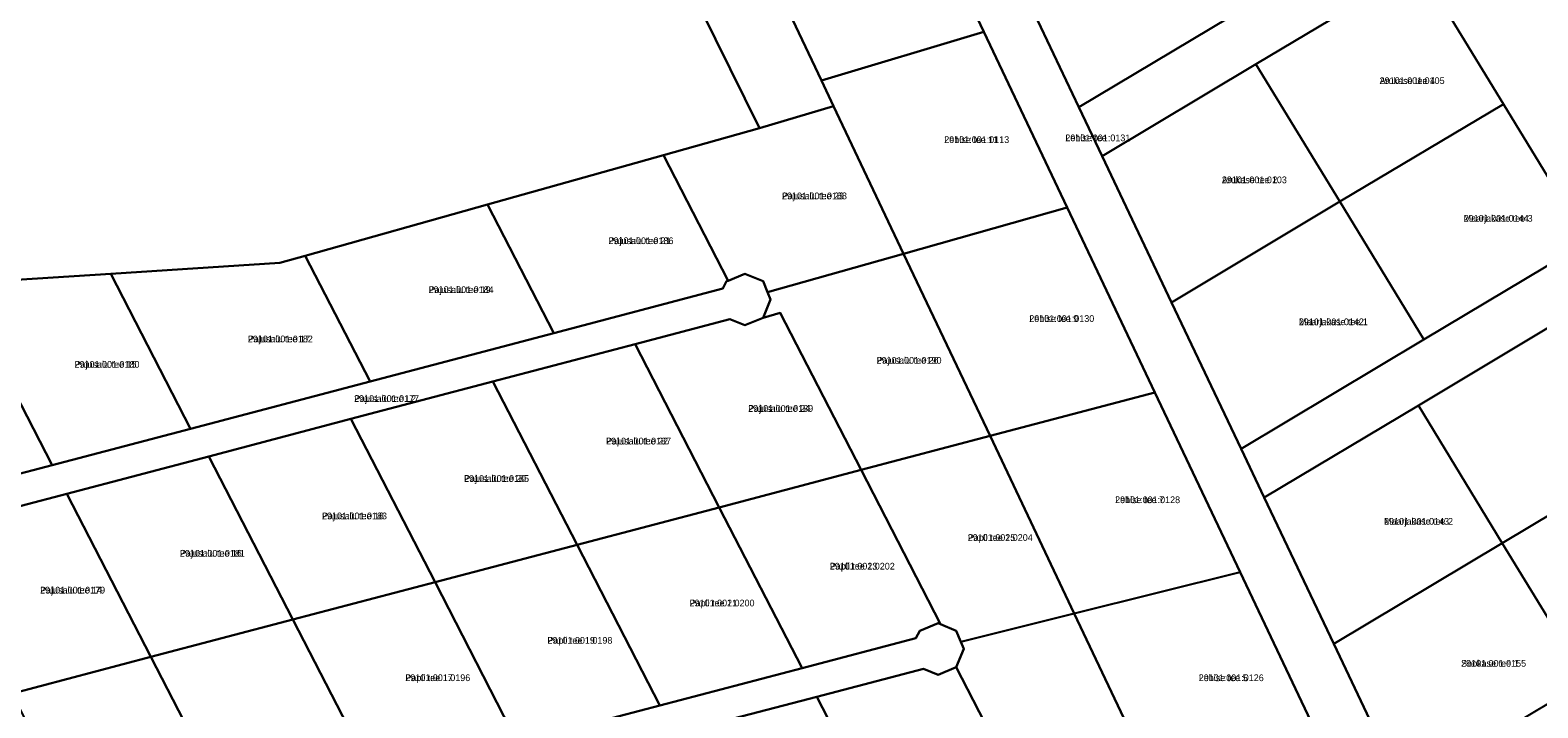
# Model space of a CAD drawing. Extents: x 660838 to 697091, y 6455678 to 6479886.
# Drawn here: x 664095.1 to 664431.6, y 6468450.3 to 6468601.6 of the extents above; entities that cross this region are included whole.
import ezdxf

# ---------------------------------------------------------------- set-up
doc = ezdxf.new("R2010")
doc.units = 0
for name, color, linetype in [('L_AADRESS', 7, 'Continuous'), ('PIIR', 7, 'Continuous'), ('TUNNUS', 7, 'Continuous')]:
    doc.layers.add(name, color=color, linetype=linetype)

msp = doc.modelspace()

# ---------------------------------------------------------------- linework, layer by layer
at = {"layer": 'PIIR'}
for points in [[(664334.36, 6468573.5), (664329.19, 6468584.39), (664383.94, 6468617.12), (664425.99, 6468642.26), (664402.11, 6468682.2), (664384.01, 6468725.17), (664387.69, 6468726.72), (664405.69, 6468684.01), (664429.42, 6468644.31), (664469.91, 6468668.51), (664513.25, 6468694.41), (664564.33, 6468724.95), (664570.59, 6468714.71), (664534.84, 6468693.34), (664498.89, 6468671.85), (664463.15, 6468650.49), (664443.8, 6468638.93), (664438.64, 6468635.85), (664405.17, 6468615.83), (664368.7, 6468594.03)], [(664257.87, 6468579.74), (664208.84, 6468678.98), (664212.4, 6468677.43), (664216.46, 6468679.11), (664218.15, 6468683.18), (664216.46, 6468687.24), (664214.39, 6468688.1), (664223.91, 6468691.15), (664226.94, 6468684.75), (664229.48, 6468679.37), (664252.28, 6468631.31), (664271.72, 6468590.32), (664274.43, 6468584.62)], [(664156.44, 6468551.21), (664150.84, 6468549.63), (664113.09, 6468547.2), (664079.12, 6468545.02), (664052.46, 6468543.3), (664045.73, 6468542.87), (664045.52, 6468542.86), (664020.16, 6468591.48), (664010.85, 6468610.16), (664011.82, 6468610.76), (664029.43, 6468621.6), (664208.84, 6468678.98), (664257.87, 6468579.74), (664236.44, 6468573.71), (664197.17, 6468562.66)], [(664370.55, 6468497.27), (664365.38, 6468508.16), (664406.2, 6468532.57), (664442.67, 6468554.37), (664500.65, 6468589.03), (664536.43, 6468610.43), (664572.36, 6468631.91), (664608.1, 6468653.27), (664614.35, 6468643.03), (664571.46, 6468617.39), (664528.54, 6468591.73), (664485.63, 6468566.07), (664504.37, 6468535.36), (664523.16, 6468504.58), (664519.73, 6468502.53), (664500.94, 6468533.3), (664482.19, 6468564.02), (664441.84, 6468539.89), (664404.94, 6468517.83)], [(664423.92, 6468585.1), (664405.17, 6468615.83), (664438.64, 6468635.85), (664441.25, 6468631.58), (664446.4, 6468634.66), (664443.8, 6468638.93), (664463.15, 6468650.49), (664481.9, 6468619.76), (664500.65, 6468589.03), (664442.67, 6468554.37)], [(664271.72, 6468590.32), (664252.28, 6468631.31), (664288.66, 6468641.77), (664307.92, 6468601.21)], [(664329.19, 6468584.39), (664313.61, 6468617.19), (664367.93, 6468643.89), (664383.94, 6468617.12)], [(664387.44, 6468563.32), (664368.7, 6468594.03), (664405.17, 6468615.83), (664423.92, 6468585.1)], [(664290.05, 6468551.68), (664274.43, 6468584.62), (664271.72, 6468590.32), (664307.92, 6468601.21), (664326.53, 6468562.01)], [(664349.87, 6468540.83), (664334.36, 6468573.5), (664368.7, 6468594.03), (664387.44, 6468563.32)], [(664257.87, 6468579.74), (664274.43, 6468584.62), (664290.05, 6468551.68), (664259.7, 6468543.08), (664258.69, 6468545.53), (664254.62, 6468547.21), (664250.88, 6468545.67), (664236.44, 6468573.71)], [(664406.2, 6468532.57), (664387.44, 6468563.32), (664423.92, 6468585.1), (664442.67, 6468554.37)], [(664197.17, 6468562.66), (664236.44, 6468573.71), (664250.88, 6468545.67), (664250.55, 6468545.53), (664249.71, 6468543.92), (664211.95, 6468533.97)], [(664365.38, 6468508.16), (664349.87, 6468540.83), (664387.44, 6468563.32), (664406.2, 6468532.57)], [(664156.44, 6468551.21), (664197.17, 6468562.66), (664211.95, 6468533.97), (664170.96, 6468523.18)], [(664309.35, 6468511.01), (664290.05, 6468551.68), (664326.53, 6468562.01), (664346.15, 6468520.69)], [(664150.84, 6468549.63), (664156.44, 6468551.21), (664170.96, 6468523.18), (664130.88, 6468512.62), (664113.09, 6468547.2)], [(664259.7, 6468543.08), (664290.05, 6468551.68), (664309.35, 6468511.01), (664280.61, 6468503.44), (664262.47, 6468538.49), (664258.69, 6468537.4), (664260.37, 6468541.46)], [(664250.88, 6468545.67), (664254.62, 6468547.21), (664258.69, 6468545.53), (664259.7, 6468543.08), (664260.37, 6468541.46), (664258.69, 6468537.4), (664254.62, 6468535.71), (664251.28, 6468537.09), (664230.11, 6468531.51), (664198.4, 6468523.16), (664166.7, 6468514.82), (664134.99, 6468506.46), (664103.28, 6468498.11), (664072.61, 6468490.03), (664069.8, 6468495.5), (664069.85, 6468495.51), (664069.39, 6468496.43), (664100, 6468504.49), (664130.88, 6468512.62), (664170.96, 6468523.18), (664211.95, 6468533.97), (664249.71, 6468543.92), (664250.55, 6468545.53)], [(664079.12, 6468545.02), (664113.09, 6468547.2), (664130.88, 6468512.62), (664100, 6468504.49)], [(664054.92, 6468537.99), (664052.46, 6468543.3), (664079.12, 6468545.02), (664100, 6468504.49), (664069.39, 6468496.43), (664068.29, 6468498.63), (664050.65, 6468533.28), (664049.41, 6468535.71)], [(664423.68, 6468487.09), (664404.94, 6468517.83), (664441.84, 6468539.89), (664460.59, 6468509.16)], [(664230.11, 6468531.51), (664251.28, 6468537.09), (664254.62, 6468535.71), (664258.69, 6468537.4), (664262.47, 6468538.49), (664280.61, 6468503.44), (664248.88, 6468495.08)], [(664198.4, 6468523.16), (664230.11, 6468531.51), (664248.88, 6468495.08), (664217.17, 6468486.73)], [(664166.7, 6468514.82), (664198.4, 6468523.16), (664217.17, 6468486.73), (664185.46, 6468478.38)], [(664328.13, 6468471.41), (664309.35, 6468511.01), (664346.15, 6468520.69), (664365.17, 6468480.63)], [(664386.06, 6468464.6), (664370.55, 6468497.27), (664404.94, 6468517.83), (664423.68, 6468487.09)], [(664134.99, 6468506.46), (664166.7, 6468514.82), (664185.46, 6468478.38), (664153.76, 6468470.03)], [(664280.61, 6468503.44), (664309.35, 6468511.01), (664328.13, 6468471.41), (664302.8, 6468465.1), (664301.79, 6468467.54), (664298.27, 6468468.99)], [(664103.28, 6468498.11), (664134.99, 6468506.46), (664153.76, 6468470.03), (664122.04, 6468461.69)], [(664442.44, 6468456.35), (664423.68, 6468487.09), (664460.59, 6468509.16), (664479.35, 6468478.41)], [(664248.88, 6468495.08), (664280.61, 6468503.44), (664298.27, 6468468.99), (664297.73, 6468469.22), (664293.66, 6468467.54), (664292.77, 6468465.85), (664267.38, 6468459.19)], [(664072.61, 6468490.03), (664103.28, 6468498.11), (664122.04, 6468461.69), (664091.12, 6468453.52), (664083.83, 6468468.15)], [(664217.17, 6468486.73), (664248.88, 6468495.08), (664267.38, 6468459.19), (664235.65, 6468450.87)], [(664185.46, 6468478.38), (664217.17, 6468486.73), (664235.65, 6468450.87), (664203.9, 6468442.55)], [(664401.57, 6468431.93), (664386.06, 6468464.6), (664423.68, 6468487.09), (664442.44, 6468456.35)], [(664346.87, 6468431.87), (664328.13, 6468471.41), (664365.17, 6468480.63), (664383.72, 6468441.55)], [(664153.76, 6468470.03), (664185.46, 6468478.38), (664203.9, 6468442.55), (664172.21, 6468434.24)], [(664293.66, 6468467.54), (664297.73, 6468469.22), (664298.27, 6468468.99), (664301.79, 6468467.54), (664302.8, 6468465.1), (664303.48, 6468463.47), (664301.8, 6468459.42), (664297.73, 6468457.72), (664294.48, 6468459.06), (664270.67, 6468452.82), (664238.94, 6468444.5), (664207.18, 6468436.17), (664175.5, 6468427.87), (664143.75, 6468419.54), (664112.73, 6468411.41), (664109.42, 6468417.78), (664140.45, 6468425.92), (664172.21, 6468434.24), (664203.9, 6468442.55), (664235.65, 6468450.87), (664267.38, 6468459.19), (664292.77, 6468465.85)], [(664122.04, 6468461.69), (664153.76, 6468470.03), (664172.21, 6468434.24), (664140.45, 6468425.92)], [(664302.8, 6468465.1), (664328.13, 6468471.41), (664346.87, 6468431.87), (664319.63, 6468424.72), (664301.8, 6468459.42), (664303.48, 6468463.47)], [(664091.12, 6468453.52), (664122.04, 6468461.69), (664140.45, 6468425.92), (664109.42, 6468417.78), (664108.26, 6468419.99), (664095.38, 6468444.97)], [(664297.73, 6468457.72), (664301.8, 6468459.42), (664319.63, 6468424.72), (664319.03, 6468424.56), (664289.26, 6468416.74), (664270.67, 6468452.82), (664294.48, 6468459.06)], [(664238.94, 6468444.5), (664270.67, 6468452.82), (664289.26, 6468416.74), (664288.14, 6468416.45), (664257.52, 6468408.41)]]:
    msp.add_lwpolyline(points, close=True, dxfattribs=at)
msp.add_lwpolyline([(664313.61, 6468617.19), (664329.19, 6468584.39), (664334.36, 6468573.5), (664349.87, 6468540.83), (664365.38, 6468508.16), (664370.55, 6468497.27), (664386.06, 6468464.6), (664401.57, 6468431.93), (664406.74, 6468421.04), (664422.25, 6468388.37), (664437.07, 6468357.15), (664426.82, 6468350.79), (664402.72, 6468401.53), (664383.72, 6468441.55), (664365.17, 6468480.63), (664346.15, 6468520.69), (664326.53, 6468562.01), (664307.92, 6468601.21), (664288.66, 6468641.77)], dxfattribs=at)

# ---------------------------------------------------------------- texts
at = {"layer": 'L_AADRESS'}
for s, p in [('Arukase tee 4', (664396.3, 6468589.57)), ('Lehise tee 11', (664299.12, 6468576.41)), ('Lehise tee', (664326.15, 6468576.8)), ('Arukase tee 2', (664361.09, 6468567.43)), ('Pajusalu tee 23', (664262.9, 6468563.85)), ('Maarjakase tee 3', (664415.06, 6468558.84)), ('Pajusalu tee 21', (664224.19, 6468553.84)), ('Pajusalu tee 19', (664184.04, 6468542.92)), ('Lehise tee 9', (664318.1, 6468536.47)), ('Maarjakase tee 1', (664378.28, 6468535.74)), ('Pajusalu tee 17', (664143.69, 6468531.92)), ('Pajusalu tee 15', (664105, 6468526.24)), ('Pajusalu tee 26', (664284.02, 6468527.15)), ('Pajusalu tee L2', (664167.4, 6468518.62)), ('Pajusalu tee 24', (664255.36, 6468516.4)), ('Pajusalu tee 22', (664223.64, 6468509.12)), ('Pajusalu tee 20', (664191.94, 6468500.77)), ('Lehise tee 7', (664337.26, 6468496.02)), ('Pajusalu tee 18', (664160.23, 6468492.42)), ('Maarjakase tee 2', (664397.29, 6468491.21)), ('Papli tee 25', (664304.37, 6468487.59)), ('Pajusalu tee 16', (664128.52, 6468484.08)), ('Papli tee 23', (664273.58, 6468481.2)), ('Pajusalu tee 14', (664097.32, 6468475.85)), ('Papli tee 21', (664242.28, 6468472.97)), ('Papli tee 19', (664210.55, 6468464.64)), ('Sookase tee 1', (664414.49, 6468459.51)), ('Papli tee 17', (664178.83, 6468456.3)), ('Lehise tee 5', (664355.93, 6468456.29))]:
    msp.add_text(s, height=1.5, dxfattribs=at).set_placement(p)
at = {"layer": 'TUNNUS'}
for s, p in [('29101:001:0105', (664396.3, 6468589.57)), ('29101:001:0113', (664299.12, 6468576.41)), ('29101:001:0131', (664326.15, 6468576.8)), ('29101:001:0103', (664361.09, 6468567.43)), ('29101:001:0188', (664262.9, 6468563.85)), ('29101:001:0144', (664415.06, 6468558.84)), ('29101:001:0186', (664224.19, 6468553.84)), ('29101:001:0184', (664184.04, 6468542.92)), ('29101:001:0130', (664318.1, 6468536.47)), ('29101:001:0142', (664378.28, 6468535.74)), ('29101:001:0182', (664143.69, 6468531.92)), ('29101:001:0180', (664105, 6468526.24)), ('29101:001:0190', (664284.02, 6468527.15)), ('29101:001:0177', (664167.4, 6468518.62)), ('29101:001:0189', (664255.36, 6468516.4)), ('29101:001:0187', (664223.64, 6468509.12)), ('29101:001:0185', (664191.94, 6468500.77)), ('29101:001:0128', (664337.26, 6468496.02)), ('29101:001:0183', (664160.23, 6468492.42)), ('29101:001:0143', (664397.29, 6468491.21)), ('29101:001:0204', (664304.37, 6468487.59)), ('29101:001:0181', (664128.52, 6468484.08)), ('29101:001:0202', (664273.58, 6468481.2)), ('29101:001:0179', (664097.32, 6468475.85)), ('29101:001:0200', (664242.28, 6468472.97)), ('29101:001:0198', (664210.55, 6468464.64)), ('29101:001:0155', (664414.49, 6468459.51)), ('29101:001:0196', (664178.83, 6468456.3)), ('29101:001:0126', (664355.93, 6468456.29))]:
    msp.add_text(s, height=1.5, dxfattribs=at).set_placement(p)

doc.saveas('drawing.dxf')
